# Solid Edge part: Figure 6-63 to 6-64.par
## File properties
Author: CADCIM
Template: Iso Part.par
Last saved by: CADCIM
Revision: 4
Application: Solid Edge
Accuracy: 0.990
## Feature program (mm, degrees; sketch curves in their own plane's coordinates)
pattern "PatternOccurrence_1"  YCount = 3; XOffset = 23.75 mm; YOffset = 31.7352 mm
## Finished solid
Body 1: solid body, 21 faces, 42 edges, 8 vertices.
  Faces by surface: cylinder 15, plane 6
  Edges by curve: circle 30, line 12
Bounding box of the edges (mm): 98.930 x 137.043 x 25.113, from (-46.9547, -70.8435, -12.5566) to (51.9752, 66.1992, 12.5566).
Cylindrical faces by radius (mm): R6.4212 x15
Planar faces by outward normal: +x 1, +y 1, +z 1, -x 1, -y 1, -z 1
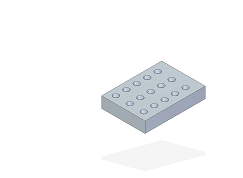
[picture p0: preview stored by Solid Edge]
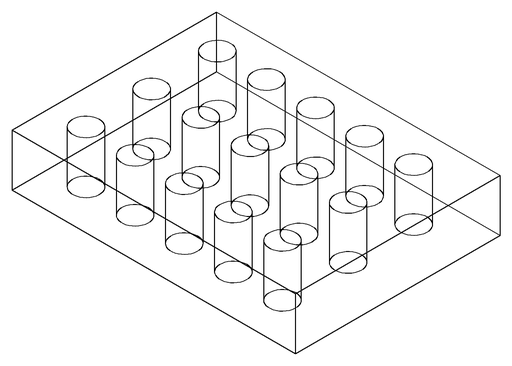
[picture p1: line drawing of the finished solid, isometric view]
